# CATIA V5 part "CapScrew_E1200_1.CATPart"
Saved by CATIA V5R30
Part number: Sroub_M5x30
Nomenclature: E1200/5x30
Description: MEUSBURGER
Publications: "DrillHole", "TapHole", "Base"
Bounding box of the stored display mesh (mm): x -4.247 to 4.247, y -4.244 to 4.244, z -5 to 30
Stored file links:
  E:\Bakalarka\Model\Forma_v7\CapScrew_E1200_1.CATPart
  E:\dev\MoldDesign\intel_a\startup\components\MoldCatalog\CapScrew\Meusburger\CapScrew_E1200\TableE1200.txt
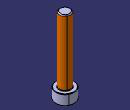
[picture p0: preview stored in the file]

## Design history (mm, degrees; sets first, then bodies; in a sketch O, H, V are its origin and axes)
Parameters
  Ref = "E1200/5x30" {design table}
  L = 30 mm {design table}
  D = 5 mm {design table}
  D1 = 5 mm {design table}
  D3 = 8.5 mm {design table}
  L1 = 30 mm {design table}
  L2 = 22 mm {design table}
  L3 = 5 mm {design table}
  SW = 4 mm {design table}
  dkren = 4.02 mm {design table}
  L4 = 2.5 mm {design table}
  R = 0.2 mm {design table}
  R1 = 0.5 mm {design table}
  F = 0.4 mm {design table}
  kdkern = 4.13 mm {design table}
  kd1 = 5.5 mm {design table}
  kl1 = 15 mm {design table}
  kd3 = 9.5 mm {design table}
  kl3 = 6 mm {design table}
  kl = 40 mm {design table}
  c = 4 mm {design table}
  ThreadString = "M5" {design table}
  Mat = "" {design table}
  HeatTreat = "" {design table}
  SupplierRef = "Meusburger 2017"
  BmpRef = "F_MldCapScrewLD"
  DrillHole_Length = 225 mm
  HeadThick = 5 mm {= L3}
  HeadDiam = 8.5 mm {= D3}
  ScrewThread = 22 mm {= Thread1.Depth}
  ScrewPitch = 0.8 mm {= Thread1.Pitch}
Set1 "BaseBody"
  Point1 "Base": (0, 0, 0)
  Plane1: type Offset, RefPlane xy-plane, Offset 225 {= DrillHole_Length}, reversed
Body1 "PartBody" (main body)
  Sketch1 on yz-plane, origin (0, 0, 0), H (0, 0, -1), V (0, 1, 0)
    point P1 (5, 0)
    line L1 (5, 0) -> (5, -4.25)
    line L2 (5, -4.25) -> (0, -4.25)
    line L3 (0, -4.25) -> (0, -2.5)
    point P5 (0, -2.5)
    line L4 (0, -2.5) -> (-30, -2.5)
    line L5 (-30, -2.5) -> (-30, 0)
    point P7 (-30, 0)
    axis line L6 (-30, 0) -> (5, 0)
    point P8 (5, 0)
    construction line L7 (0, -2.5) -> (0, -2.5)
    line L8 (0, 0) -> (-30, 0)
    point P9 (-30, -2.5)
    point P10 (-30, -2.5)
    line L9 (0, 0) -> (5, 0)
    length L1 = 4.25 {= D3 /2}
    distance L1 L3 = 5 {= L3}
    distance L4 L6 = 2.5 {= D /2}
    distance L3 L5 = 30 {= L}
    distance L5 P5 = 30 {= L1}
    coincidence: P1 L6, L6 H, P8 L1, P9 P10, P7 L5, L3 V
    vertical: L1 V, L3 V, L5 V
    horizontal: L2 H, L4 H, L7 H, L8 H, L9 H
  Shaft1: profile Sketch1, axis Sketch1.L6, angle 360
  Sketch2 on face of Shaft1 from Sketch1.L1, origin (0, 0, -5), H (1, 0, 0), V (0, -1, 0)
    point P1 (-1.1547, -2)
    point P2 (1.1547, -2)
    point P3 (2.3094, 0)
    point P4 (1.1547, 2)
    point P5 (-1.1547, 2)
    point P6 (-2.3094, 0)
    point P7 (0, -2)
    line L1 (-1.1547, -2) -> (1.1547, -2)
    line L2 (1.1547, -2) -> (2.3094, 0)
    line L3 (2.3094, 0) -> (1.1547, 2)
    line L4 (1.1547, 2) -> (-1.1547, 2)
    line L5 (-1.1547, 2) -> (-2.3094, 0)
    line L6 (-2.3094, 0) -> (-1.1547, -2)
    construction line L7 (0, 0) -> (0, -2)
    construction circle A1 centre (0, 0) radius 2.3094
    construction arc A2 centre (-1.1547, 2) radius 2.3094 from (1.1547, 2) to (-2.3094, 0) cw
    construction arc A3 centre (1.1547, -2) radius 2.3094 from (2.3094, 0) to (-1.1547, -2) ccw
    point P8 (-1.1547, 2)
    point P9 (1.1547, -2)
    distance L1 L4 = 4 {= SW}
    coincidence: A1 P1, A1 P2, A1 P3, A1 P4, A1 P5, A1 P6, A2 P4, A2 P6, A2 O, P8 P5, A3 P3, A3 P1, A3 O, P9 P2, P3 H
    midpoint: P7 L1
  Pocket1: profile Sketch2, direction (0, 0, 1), length 2.5 {= L4}
  Thread1: "M5", diameter 5, depth 22 {= L2}, pitch 0.8, on face of Shaft1 from Sketch1.L4, from face of Shaft1 from Sketch1.L5
  Fillet1: radius 0.5 {= R1}, on edge [face of Shaft1 from Sketch1.L2 | face of Shaft1 from Sketch1.L1]
  Fillet2: radius 0.2 {= R}, on edge [face of Shaft1 from Sketch1.L3 | face of Shaft1 from Sketch1.L2]
  Fillet3: radius 0.2 {= R}, on edge [face of Shaft1 from Sketch1.L4 | face of Shaft1 from Sketch1.L3]
  Chamfer1: length 0.4 {= F}, angle 45, on edge [face of Shaft1 from Sketch1.L5 | face of Shaft1 from Sketch1.L4]
Body2 "DrillHole"
  Sketch3 on Plane1, origin (22.3066, -22.3066, -225), H (1, 0, 0), V (0, 1, 0)
    point P1 (-22.3066, 22.3066)
    reference projected circle E1 centre (-22.3066, 22.3066) radius 4.25 from edge [face of Shaft1 from Sketch1.L3 | face of Shaft1 from Sketch1.L2]
    concentricity: E1 P1
  Hole1: placed by Sketch3, at (0, 0, -225) direction (0, 0, 1), diameter 5.5 {= kd1}, depth 255 {= DrillHole_Length +L1}, counterbore diameter 9.5 {= kd3}, counterbore depth 225 {= DrillHole_Length}
Body3 "TapHole"
  Sketch4 on Plane1, origin (0, 0, -225), H (1, 0, 0), V (0, 1, 0)
    point P1 (0, 0)
    reference projected point E1 (0, 0) from Point1
    coincidence: E1 P1
  Hole2: placed by Sketch4, at (0, 0, -225) direction (0, 0, 1), diameter 4.134, depth 265 {= DrillHole_Length +kl}, V-bottom angle 120, threaded "M5", thread diameter 5, thread depth 265 {= DrillHole_Length +kl}, pitch 0.8
Relations
  design table "TableE1200", configuration 37, drives Ref, L, D, D1, D3, L1, L2, L3, SW, dkren, L4, R, R1, F, kdkern, kd1, kl1, kd3, kl3, kl, c, ThreadString, Mat, HeatTreat
  Thread1.ThreadDescription = ThreadString
  Hole2.ThreadDescription = ThreadString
